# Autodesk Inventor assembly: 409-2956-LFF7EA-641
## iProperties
Created: 2010-06
Part Number: 409-2956-LFF7EA-641
Document SubType Name: Weldment
Designer: S. Boerckel
Weld Material: Welded Aluminum-6061
Mass: 29330.7 g
Surface Area: 20462.2 cm^2
Volume: 3731.64 cm^3
Density: 7.86 g/cm^3
Description: PRESSURE DIFFERENTIAL MOUNT
User Status: WELD
Material: WELDMENT
SMR: =<Material>
Author: S. Boerckel
Revision Number: B
Subject: DEMIN WATER FORWARDING PUMP SKID-7EA
Title: PRESSURE DIFFERENTIAL MOUNT
